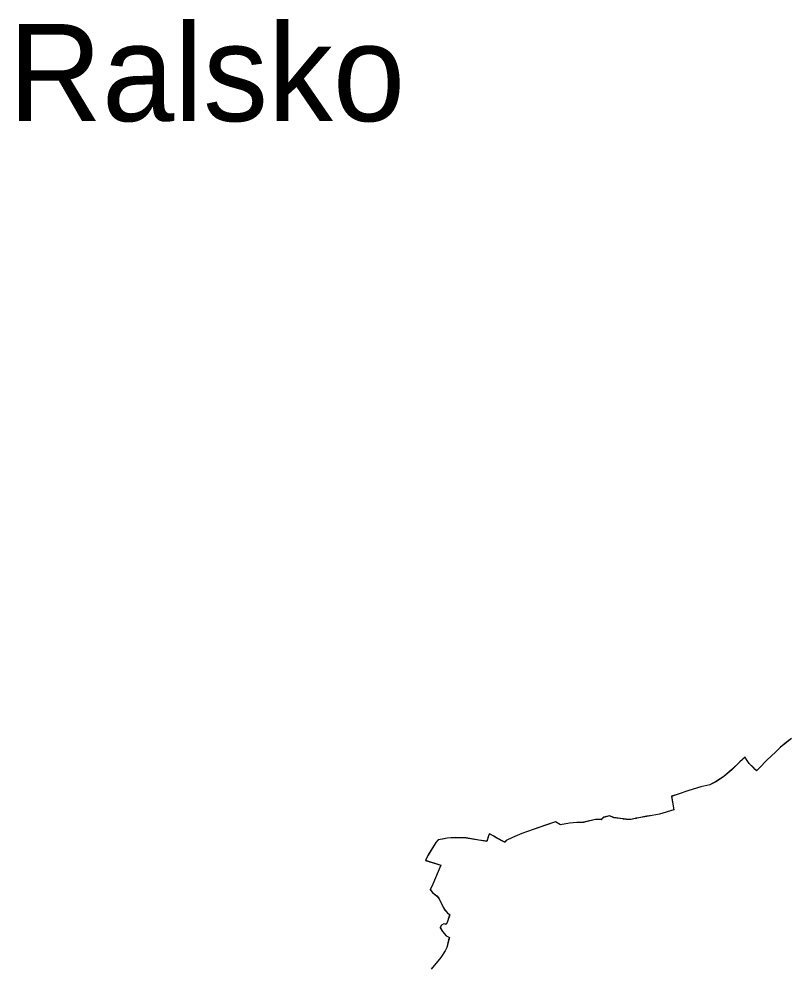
# Model space of a CAD drawing. Extents: x -742239 to -650174, y -1010569 to -945473.
# Drawn here: x -707087 to -703166, y -994899 to -990079 of the extents above; entities that cross this region are included whole.
import ezdxf

# ---------------------------------------------------------------- set-up
doc = ezdxf.new("R2010")
doc.units = 0
for name, color, linetype in [('Hranice kraje', 7, 'Continuous'), ('Hranice obcí', 7, 'Continuous'), ('IMPLICIT', 7, 'Continuous'), ('Obce II_stupne', 7, 'Continuous'), ('Obce III_stupne', 7, 'Continuous'), ('Obce ostaní', 7, 'Continuous'), ('Obce popis', 7, 'Continuous')]:
    doc.layers.add(name, color=color, linetype=linetype)

# ---------------------------------------------------------------- blocks, each defined once
blk = doc.blocks.new('BLK000')
at = {"layer": 'IMPLICIT'}
for points in [[(-1512.6, -4020.7), (-1515.5, -4022.9), (-1518.9, -4025.6), (-1521.8, -4028.5), (-1523.7, -4030.2), (-1526.7, -4033.1), (-1530.6, -4037.1), (-1532.4, -4039), (-1532.7, -4038.6), (-1533.2, -4038.2), (-1534.4, -4036.9), (-1536.6, -4034.8), (-1538.5, -4031.9), (-1538.8, -4031.3), (-1541.8, -4033.9), (-1546.4, -4038.3), (-1551, -4042.2), (-1555.1, -4044.9), (-1558.8, -4046.9), (-1563.9, -4048.1), (-1570.7, -4050.2), (-1577.3, -4052.4), (-1580.6, -4053.4), (-1579.3, -4061.1), (-1587.4, -4063.5), (-1591.5, -4064.2), (-1594.6, -4064.7), (-1600.1, -4065.7), (-1600.6, -4065.8), (-1601.1, -4066), (-1603.5, -4066.6), (-1606.3, -4066.4), (-1607.7, -4066.2), (-1608.2, -4066.2), (-1613.2, -4065.5), (-1615.7, -4064.5), (-1619.1, -4065.3), (-1620.5, -4066.6), (-1621.9, -4066.5), (-1623.7, -4066.5), (-1630.4, -4068.1), (-1634.2, -4068.3), (-1638.3, -4068.6), (-1643.4, -4069.5), (-1646.3, -4067.8), (-1651.8, -4069.8), (-1659, -4072.2), (-1665.3, -4074.4), (-1670.6, -4076.7), (-1674.2, -4078.4), (-1675.1, -4079.4), (-1679.8, -4076.9), (-1681.2, -4075.9)], [(-1681.2, -4075.9), (-1683.6, -4074.6), (-1684.1, -4075.3), (-1685.2, -4078.9), (-1689.7, -4078.3), (-1696.9, -4077), (-1703.2, -4076.8), (-1707.6, -4077.1), (-1710.4, -4077.6), (-1712.8, -4078.1), (-1714, -4079.5), (-1718.4, -4086.6), (-1719.9, -4089.6), (-1711.2, -4092.4), (-1715.7, -4103.2), (-1717.3, -4106.3), (-1715.9, -4107.9), (-1713.6, -4109.8), (-1712.3, -4111.2), (-1711.1, -4114), (-1708.9, -4117.8), (-1707.7, -4119.2), (-1706.2, -4120.5), (-1707.5, -4124.3), (-1708.2, -4125.9), (-1709.6, -4125.6), (-1710.8, -4126.4), (-1711.6, -4127.8), (-1710.3, -4130), (-1708.3, -4132.4), (-1706.3, -4133.4), (-1706.8, -4134.7), (-1707.8, -4139.1), (-1708.8, -4141), (-1711.2, -4144.8), (-1716.7, -4151.3)]]:
    blk.add_lwpolyline(points, dxfattribs=at)

msp = doc.modelspace()

# ---------------------------------------------------------------- linework, layer by layer
at = {"layer": 'Hranice obcí'}
for points in [[(-703148.6, -993749.2), (-703175.3, -993768.9), (-703205.2, -993793.1), (-703231.5, -993819.4), (-703248.8, -993835.1), (-703276.1, -993861.2), (-703310.4, -993897.2), (-703326.8, -993914.1), (-703330, -993910.8), (-703334.1, -993906.6), (-703345.4, -993894.8), (-703364.7, -993876.5), (-703381.5, -993849.8), (-703384.9, -993844.4), (-703411.4, -993868.3), (-703452.8, -993908.1), (-703494, -993942.8), (-703531.3, -993967.6), (-703565, -993985.2), (-703610.7, -993995.7), (-703671.9, -994014.5), (-703730.7, -994034.3), (-703760.8, -994043.5), (-703749.3, -994112.7), (-703822.3, -994134.8), (-703859.2, -994141.2), (-703886.4, -994145.5), (-703936.6, -994154.7), (-703940.7, -994155.7), (-703945.4, -994156.8), (-703967.1, -994162.3), (-703992.2, -994160.8), (-704004.5, -994159.1), (-704009, -994158.5), (-704053.8, -994152.5), (-704076.5, -994143.4), (-704107.1, -994151.2), (-704119.7, -994162.7), (-704132.8, -994161.4), (-704148.6, -994161.4), (-704209.1, -994176.2), (-704243, -994177.6), (-704280.5, -994180.8), (-704325.9, -994189), (-704351.8, -994173), (-704401.9, -994191), (-704466.1, -994212.7), (-704523, -994232.6), (-704571.1, -994253.4), (-704603.1, -994268.6), (-704611.3, -994278), (-704653.5, -994254.8), (-704666.6, -994246.1), (-704687.9, -994234.3), (-704692.3, -994240.4), (-704702.6, -994273.4), (-704743, -994267.7), (-704807.8, -994256.1), (-704864.1, -994254.5), (-704903.6, -994257.1), (-704929.2, -994261.8), (-704950.7, -994265.7), (-704961.3, -994278.3), (-705001.3, -994342.7), (-705014.9, -994369.9), (-704936.3, -994394.7), (-704977.1, -994492.2), (-704991.4, -994520), (-704978.8, -994534.5), (-704957.6, -994551.1), (-704946.1, -994563.7), (-704935.1, -994588.9), (-704915.7, -994623.7), (-704904.6, -994636), (-704891.6, -994647.8), (-704903.1, -994681.6)], [(-704903.1, -994681.6), (-704909.1, -994696.4), (-704921.7, -994693.3), (-704932.4, -994700.4), (-704939.4, -994713.7), (-704928.4, -994733.4), (-704909.9, -994754.7), (-704891.9, -994763.8), (-704896.6, -994775.6), (-704905.8, -994814.8), (-704914.5, -994831.7), (-704936.5, -994866), (-704985.9, -994924.5)]]:
    msp.add_lwpolyline(points, dxfattribs=at)
at = {"layer": 'Obce II_stupne'}
for points in [[(-703148.6, -993749.2), (-703175.3, -993768.9), (-703205.2, -993793.1), (-703231.5, -993819.4), (-703248.8, -993835.1), (-703276.1, -993861.2), (-703310.4, -993897.2), (-703326.8, -993914.1), (-703330, -993910.8), (-703334.1, -993906.6), (-703345.4, -993894.8), (-703364.7, -993876.5), (-703381.5, -993849.8), (-703384.9, -993844.4), (-703411.4, -993868.3), (-703452.8, -993908.1), (-703494, -993942.8), (-703531.3, -993967.6), (-703565, -993985.2), (-703610.7, -993995.7), (-703671.9, -994014.5), (-703730.7, -994034.3), (-703760.8, -994043.5), (-703749.3, -994112.7), (-703822.3, -994134.8), (-703859.2, -994141.2), (-703886.4, -994145.5), (-703936.6, -994154.7), (-703940.7, -994155.7), (-703945.4, -994156.8), (-703967.1, -994162.3), (-703992.2, -994160.8), (-704004.5, -994159.1), (-704009, -994158.5), (-704053.8, -994152.5), (-704076.5, -994143.4), (-704107.1, -994151.2), (-704119.7, -994162.7), (-704132.8, -994161.4), (-704148.6, -994161.4), (-704209.1, -994176.2), (-704243, -994177.6), (-704280.5, -994180.8), (-704325.9, -994189), (-704351.8, -994173), (-704401.9, -994191), (-704466.1, -994212.7), (-704523, -994232.6), (-704571.1, -994253.4), (-704603.1, -994268.6), (-704611.3, -994278), (-704653.5, -994254.8), (-704666.6, -994246.1), (-704687.9, -994234.3), (-704692.3, -994240.4), (-704702.6, -994273.4), (-704743, -994267.7), (-704807.8, -994256.1), (-704864.1, -994254.5), (-704903.6, -994257.1), (-704929.2, -994261.8), (-704950.7, -994265.7), (-704961.3, -994278.3), (-705001.3, -994342.7), (-705014.9, -994369.9), (-704936.3, -994394.7), (-704977.1, -994492.2), (-704991.4, -994520), (-704978.8, -994534.5), (-704957.6, -994551.1), (-704946.1, -994563.7), (-704935.1, -994588.9), (-704915.7, -994623.7), (-704904.6, -994636), (-704891.6, -994647.8), (-704903.1, -994681.6)], [(-704903.1, -994681.6), (-704909.1, -994696.4), (-704921.7, -994693.3), (-704932.4, -994700.4), (-704939.4, -994713.7), (-704928.4, -994733.4), (-704909.9, -994754.7), (-704891.9, -994763.8), (-704896.6, -994775.6), (-704905.8, -994814.8), (-704914.5, -994831.7), (-704936.5, -994866), (-704985.9, -994924.5)]]:
    msp.add_lwpolyline(points, dxfattribs=at)
at = {"layer": 'Obce III_stupne'}
for points in [[(-703148.6, -993749.2), (-703175.3, -993768.9), (-703205.2, -993793.1), (-703231.5, -993819.4), (-703248.8, -993835.1), (-703276.1, -993861.2), (-703310.4, -993897.2), (-703326.8, -993914.1), (-703330, -993910.8), (-703334.1, -993906.6), (-703345.4, -993894.8), (-703364.7, -993876.5), (-703381.5, -993849.8), (-703384.9, -993844.4), (-703411.4, -993868.3), (-703452.8, -993908.1), (-703494, -993942.8), (-703531.3, -993967.6), (-703565, -993985.2), (-703610.7, -993995.7), (-703671.9, -994014.5), (-703730.7, -994034.3), (-703760.8, -994043.5), (-703749.3, -994112.7), (-703822.3, -994134.8), (-703859.2, -994141.2), (-703886.4, -994145.5), (-703936.6, -994154.7), (-703940.7, -994155.7), (-703945.4, -994156.8), (-703967.1, -994162.3), (-703992.2, -994160.8), (-704004.5, -994159.1), (-704009, -994158.5), (-704053.8, -994152.5), (-704076.5, -994143.4), (-704107.1, -994151.2), (-704119.7, -994162.7), (-704132.8, -994161.4), (-704148.6, -994161.4), (-704209.1, -994176.2), (-704243, -994177.6), (-704280.5, -994180.8), (-704325.9, -994189), (-704351.8, -994173), (-704401.9, -994191), (-704466.1, -994212.7), (-704523, -994232.6), (-704571.1, -994253.4), (-704603.1, -994268.6), (-704611.3, -994278), (-704653.5, -994254.8), (-704666.6, -994246.1), (-704687.9, -994234.3), (-704692.3, -994240.4), (-704702.6, -994273.4), (-704743, -994267.7), (-704807.8, -994256.1), (-704864.1, -994254.5), (-704903.6, -994257.1)], [(-704903.6, -994257.1), (-704929.2, -994261.8), (-704950.7, -994265.7), (-704961.3, -994278.3), (-705001.3, -994342.7), (-705014.9, -994369.9), (-704936.3, -994394.7), (-704977.1, -994492.2), (-704991.4, -994520), (-704978.8, -994534.5), (-704957.6, -994551.1), (-704946.1, -994563.7), (-704935.1, -994588.9), (-704915.7, -994623.7), (-704904.6, -994636), (-704891.6, -994647.8), (-704903.1, -994681.6), (-704909.1, -994696.4), (-704921.7, -994693.3), (-704932.4, -994700.4), (-704939.4, -994713.7), (-704928.4, -994733.4), (-704909.9, -994754.7), (-704891.9, -994763.8), (-704896.6, -994775.6), (-704905.8, -994814.8), (-704914.5, -994831.7), (-704936.5, -994866), (-704985.9, -994924.5)]]:
    msp.add_lwpolyline(points, dxfattribs=at)
at = {"layer": 'Obce ostaní'}
for points in [[(-703148.6, -993749.2), (-703175.3, -993768.9), (-703205.2, -993793.1), (-703231.5, -993819.4), (-703248.8, -993835.1), (-703276.1, -993861.2), (-703310.4, -993897.2), (-703326.8, -993914.1), (-703330, -993910.8), (-703334.1, -993906.6), (-703345.4, -993894.8), (-703364.7, -993876.5), (-703381.5, -993849.8), (-703384.9, -993844.4), (-703411.4, -993868.3), (-703452.8, -993908.1), (-703494, -993942.8), (-703531.3, -993967.6), (-703565, -993985.2), (-703610.7, -993995.7), (-703671.9, -994014.5), (-703730.7, -994034.3), (-703760.8, -994043.5), (-703749.3, -994112.7), (-703822.3, -994134.8), (-703859.2, -994141.2), (-703886.4, -994145.5), (-703936.6, -994154.7), (-703940.7, -994155.7), (-703945.4, -994156.8), (-703967.1, -994162.3), (-703992.2, -994160.8), (-704004.5, -994159.1), (-704009, -994158.5), (-704053.8, -994152.5), (-704076.5, -994143.4), (-704107.1, -994151.2), (-704119.7, -994162.7), (-704132.8, -994161.4), (-704148.6, -994161.4), (-704209.1, -994176.2), (-704243, -994177.6), (-704280.5, -994180.8), (-704325.9, -994189), (-704351.8, -994173), (-704401.9, -994191), (-704466.1, -994212.7), (-704523, -994232.6), (-704571.1, -994253.4), (-704603.1, -994268.6), (-704611.3, -994278), (-704653.5, -994254.8), (-704666.6, -994246.1), (-704687.9, -994234.3), (-704692.3, -994240.4), (-704702.6, -994273.4), (-704743, -994267.7), (-704807.8, -994256.1), (-704864.1, -994254.5), (-704903.6, -994257.1), (-704929.2, -994261.8), (-704950.7, -994265.7), (-704961.3, -994278.3), (-705001.3, -994342.7), (-705014.9, -994369.9), (-704936.3, -994394.7), (-704977.1, -994492.2), (-704991.4, -994520), (-704978.8, -994534.5), (-704957.6, -994551.1), (-704946.1, -994563.7), (-704935.1, -994588.9), (-704915.7, -994623.7), (-704904.6, -994636), (-704891.6, -994647.8), (-704903.1, -994681.6)], [(-704903.1, -994681.6), (-704909.1, -994696.4), (-704921.7, -994693.3), (-704932.4, -994700.4), (-704939.4, -994713.7), (-704928.4, -994733.4), (-704909.9, -994754.7), (-704891.9, -994763.8), (-704896.6, -994775.6), (-704905.8, -994814.8), (-704914.5, -994831.7), (-704936.5, -994866), (-704985.9, -994924.5)]]:
    msp.add_lwpolyline(points, dxfattribs=at)

# ---------------------------------------------------------------- block references
at = {"layer": 'Hranice kraje', "xscale": 9, "yscale": 9}
msp.add_blockref('BLK000', (-689535, -957562.7), dxfattribs=at)

# ---------------------------------------------------------------- texts
at = {"layer": 'Obce popis'}
msp.add_text('Ralsko', height=495, dxfattribs=at).set_placement((-707141.6, -990600.1))

doc.saveas('drawing.dxf')
